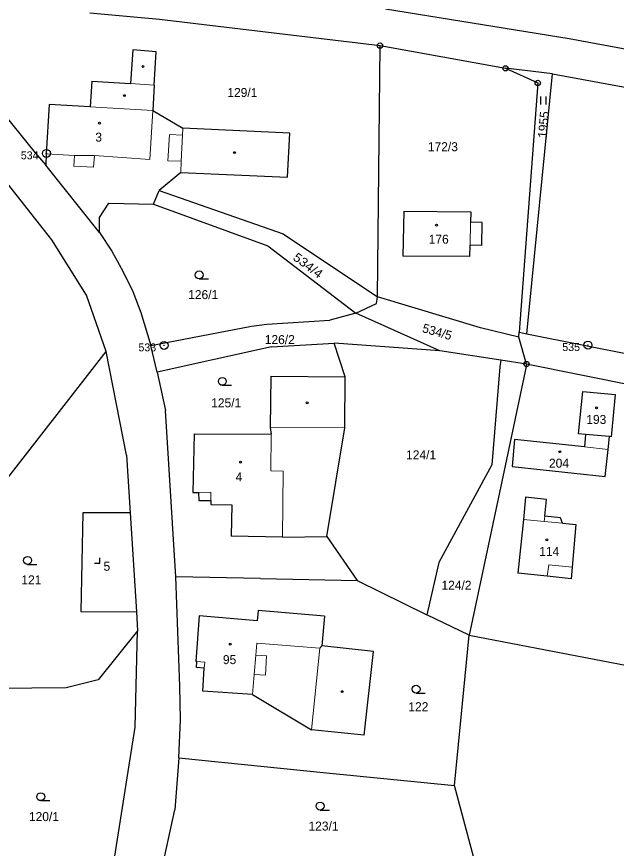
# Model space of a CAD drawing. Extents: x -601131 to -597152, y -1058536 to -1055911.
# Drawn here: x -599350.8 to -599237.3, y -1056634.8 to -1056477.3 of the extents above; entities that cross this region are included whole.
import ezdxf
from ezdxf.enums import TextEntityAlignment as Align

# ---------------------------------------------------------------- set-up
doc = ezdxf.new("R2010")
doc.units = 0
doc.header["$LTSCALE"] = 0.68
for name, color, linetype, lineweight in [('1', 7, 'Continuous', 25), ('3', 7, 'Continuous', 25), ('4', 7, 'Continuous', 13), ('5', 7, 'Continuous', 25), ('8', 7, 'Continuous', 25)]:
    doc.layers.add(name, color=color, linetype=linetype, lineweight=lineweight)
doc.layers.add('2', color=7, linetype='Continuous')

msp = doc.modelspace()

# ---------------------------------------------------------------- linework, layer by layer
at = {"layer": '1'}
for p, q in [((-599246.19, -1056481.54), (-599280.95, -1056475.91)), ((-599336.92, -1056476.64), (-599323.72, -1056477.85)), ((-599323.72, -1056477.85), (-599282, -1056482.83)), ((-599218.22, -1056486.75), (-599246.19, -1056481.54)), ((-599328.82, -1056483.65), (-599329.25, -1056490.01)), ((-599324.36, -1056483.98), (-599328.82, -1056483.65)), ((-599282.49, -1056530.39), (-599282, -1056482.83)), ((-599282, -1056482.83), (-599258.24, -1056487.13)), ((-599324.74, -1056490.29), (-599324.36, -1056483.98)), ((-599360.66, -1056486.62), (-599347.27, -1056503.12)), ((-599258.24, -1056487.13), (-599252.14, -1056489.89)), ((-599249.34, -1056488.19), (-599258.24, -1056487.13)), ((-599254.19, -1056537.36), (-599249.34, -1056488.19)), ((-599249.34, -1056488.19), (-599219.47, -1056493.64)), ((-599336.55, -1056489.57), (-599336.84, -1056494.42)), ((-599336.55, -1056489.57), (-599329.25, -1056490.01)), ((-599252.14, -1056489.89), (-599255.65, -1056537.07)), ((-599324.74, -1056490.29), (-599325.02, -1056495.08)), ((-599344.64, -1056493.95), (-599345.22, -1056503.29)), ((-599336.84, -1056494.42), (-599344.64, -1056493.95)), ((-599325.02, -1056495.08), (-599319.32, -1056498.47)), ((-599299.08, -1056499.43), (-599319.32, -1056498.47)), ((-599299.51, -1056507.74), (-599299.08, -1056499.43)), ((-599347.27, -1056503.12), (-599345.29, -1056505.47)), ((-599345.22, -1056503.29), (-599345.29, -1056505.47)), ((-599335.11, -1056518.19), (-599345.29, -1056505.47)), ((-599344.11, -1056519.56), (-599353.98, -1056507.19)), ((-599319.72, -1056506.84), (-599323.78, -1056510.24)), ((-599319.72, -1056506.84), (-599299.51, -1056507.74)), ((-599324.87, -1056512.83), (-599323.78, -1056510.24)), ((-599323.78, -1056510.24), (-599300.33, -1056518.48)), ((-599335.11, -1056515.35), (-599333.31, -1056512.65)), ((-599333.31, -1056512.65), (-599324.87, -1056512.83)), ((-599324.87, -1056512.83), (-599303.21, -1056520.71)), ((-599335.11, -1056518.19), (-599335.11, -1056515.35)), ((-599277.49, -1056514.17), (-599277.66, -1056522.67)), ((-599277.49, -1056514.17), (-599264.83, -1056514.3)), ((-599264.83, -1056514.3), (-599264.87, -1056516.25)), ((-599262.66, -1056516.34), (-599264.87, -1056516.25)), ((-599262.75, -1056520.67), (-599262.66, -1056516.34)), ((-599335.11, -1056518.19), (-599332.75, -1056521.76)), ((-599300.33, -1056518.48), (-599282.49, -1056530.39)), ((-599337.55, -1056530.08), (-599344.11, -1056519.56)), ((-599303.21, -1056520.71), (-599286.57, -1056533.49)), ((-599265.01, -1056522.74), (-599264.96, -1056520.58)), ((-599262.75, -1056520.67), (-599264.96, -1056520.58)), ((-599332.75, -1056521.76), (-599330.67, -1056525.5)), ((-599265.01, -1056522.74), (-599277.66, -1056522.67)), ((-599330.67, -1056525.5), (-599328.81, -1056529.37)), ((-599328.81, -1056529.37), (-599327.28, -1056533.36)), ((-599333.85, -1056540.74), (-599337.55, -1056530.08)), ((-599282.66, -1056531.62), (-599282.49, -1056530.39)), ((-599262.95, -1056536.25), (-599282.49, -1056530.39)), ((-599286.57, -1056533.49), (-599282.66, -1056531.62)), ((-599327.28, -1056533.36), (-599325.37, -1056539.59)), ((-599286.57, -1056533.49), (-599291.51, -1056534.81)), ((-599270.65, -1056540.61), (-599286.57, -1056533.49)), ((-599306.34, -1056535.96), (-599303.43, -1056535.56)), ((-599303.43, -1056535.56), (-599291.51, -1056534.81)), ((-599325.37, -1056539.59), (-599306.34, -1056535.96)), ((-599255.73, -1056538.03), (-599262.95, -1056536.25)), ((-599255.73, -1056538.03), (-599255.65, -1056537.07)), ((-599255.65, -1056537.07), (-599254.19, -1056537.36)), ((-599254.19, -1056537.36), (-599225.68, -1056543.1)), ((-599254.26, -1056543.1), (-599255.73, -1056538.03)), ((-599324.17, -1056544.62), (-599325.37, -1056539.59)), ((-599302.57, -1056539.87), (-599324.17, -1056544.62)), ((-599302.57, -1056539.87), (-599290.69, -1056539.12)), ((-599270.65, -1056540.61), (-599290.69, -1056539.12)), ((-599288.59, -1056545.49), (-599290.69, -1056539.12)), ((-599357.98, -1056571.68), (-599333.85, -1056540.74)), ((-599329.96, -1056560.36), (-599333.85, -1056540.74)), ((-599259.14, -1056542.37), (-599270.65, -1056540.61)), ((-599259.31, -1056543.64), (-599260.86, -1056562.16)), ((-599259.14, -1056542.37), (-599259.31, -1056543.64)), ((-599254.26, -1056543.1), (-599259.14, -1056542.37)), ((-599254.26, -1056543.1), (-599254.55, -1056544.47)), ((-599215.08, -1056551), (-599254.26, -1056543.1)), ((-599324.17, -1056544.62), (-599322.61, -1056551.91)), ((-599302.7, -1056545.38), (-599302.78, -1056555.13)), ((-599302.7, -1056545.38), (-599288.59, -1056545.49)), ((-599288.64, -1056555.18), (-599288.59, -1056545.49)), ((-599244.41, -1056556.29), (-599243.61, -1056548.27)), ((-599243.61, -1056548.27), (-599237.48, -1056548.88)), ((-599237.48, -1056548.88), (-599238.27, -1056556.87)), ((-599320.65, -1056583.35), (-599322.61, -1056551.91)), ((-599317.21, -1056556.29), (-599317.45, -1056567.4)), ((-599317.21, -1056556.29), (-599302.62, -1056556.39)), ((-599302.78, -1056555.13), (-599302.62, -1056556.39)), ((-599292.09, -1056575.75), (-599288.64, -1056555.18)), ((-599243.1, -1056556.41), (-599244.41, -1056556.29)), ((-599243.1, -1056556.41), (-599243.32, -1056558.79)), ((-599238.57, -1056556.84), (-599243.1, -1056556.41)), ((-599238.82, -1056559.27), (-599238.57, -1056556.84)), ((-599238.27, -1056556.87), (-599238.57, -1056556.84)), ((-599329.96, -1056560.36), (-599329.28, -1056571.26)), ((-599260.86, -1056562.16), (-599270.89, -1056580.69)), ((-599317.45, -1056567.4), (-599316.39, -1056567.39)), ((-599316.39, -1056567.39), (-599316.3, -1056568.93)), ((-599254.43, -1056568.31), (-599254.82, -1056572.53)), ((-599250.5, -1056568.76), (-599254.43, -1056568.31)), ((-599250.82, -1056571.87), (-599250.5, -1056568.76)), ((-599316.3, -1056568.93), (-599314, -1056568.94)), ((-599314, -1056568.94), (-599314, -1056569.68)), ((-599314, -1056569.68), (-599310.07, -1056569.74)), ((-599310.07, -1056569.74), (-599310.16, -1056575.67)), ((-599338.28, -1056571.26), (-599338.64, -1056589.94)), ((-599329.28, -1056571.26), (-599338.28, -1056571.26)), ((-599329.28, -1056571.26), (-599328.1, -1056589.99)), ((-599247.81, -1056572.22), (-599250.82, -1056571.87)), ((-599254.82, -1056572.53), (-599255.91, -1056582.67)), ((-599247.44, -1056573.24), (-599247.81, -1056572.22)), ((-599247.44, -1056573.24), (-599244.91, -1056573.48)), ((-599244.91, -1056573.48), (-599245.63, -1056581.52)), ((-599300.47, -1056575.86), (-599310.16, -1056575.67)), ((-599300.47, -1056575.86), (-599292.09, -1056575.75)), ((-599292.09, -1056575.75), (-599286.34, -1056584.1)), ((-599270.89, -1056580.69), (-599273.11, -1056590.58)), ((-599250.38, -1056583.24), (-599255.91, -1056582.67)), ((-599245.63, -1056581.52), (-599245.83, -1056583.73)), ((-599319.9, -1056604.06), (-599320.65, -1056583.35)), ((-599304.6, -1056583.69), (-599320.65, -1056583.35)), ((-599304.6, -1056583.69), (-599286.34, -1056584.1)), ((-599286.34, -1056584.1), (-599273.11, -1056590.58)), ((-599245.83, -1056583.73), (-599250.38, -1056583.24)), ((-599338.64, -1056589.94), (-599328.1, -1056589.99)), ((-599328.1, -1056589.99), (-599327.88, -1056593.57)), ((-599316.21, -1056590.77), (-599316.88, -1056599.4)), ((-599305.25, -1056591.68), (-599316.21, -1056590.77)), ((-599305.09, -1056589.76), (-599305.25, -1056591.68)), ((-599292.52, -1056590.8), (-599305.09, -1056589.76)), ((-599292.52, -1056590.8), (-599292.99, -1056596.46)), ((-599265.11, -1056594.43), (-599273.11, -1056590.58)), ((-599327.88, -1056593.57), (-599335.38, -1056602.87)), ((-599328.38, -1056611.8), (-599327.88, -1056593.57)), ((-599267.88, -1056622.9), (-599265.11, -1056594.43)), ((-599265.11, -1056594.43), (-599225.75, -1056602)), ((-599283.26, -1056597.54), (-599292.99, -1056596.46)), ((-599285, -1056613.32), (-599283.26, -1056597.54)), ((-599316.65, -1056599.42), (-599316.88, -1056599.4)), ((-599316.72, -1056600.53), (-599316.65, -1056599.42)), ((-599315.26, -1056600.67), (-599316.72, -1056600.53)), ((-599315.57, -1056605), (-599315.26, -1056600.67)), ((-599335.38, -1056602.87), (-599341.43, -1056604.36)), ((-599341.43, -1056604.36), (-599361.21, -1056604.62)), ((-599319.77, -1056610.47), (-599319.9, -1056604.06)), ((-599306.16, -1056605.65), (-599315.57, -1056605)), ((-599306.16, -1056605.65), (-599294.97, -1056612.34)), ((-599320.06, -1056617.66), (-599319.77, -1056610.47)), ((-599332.25, -1056636.61), (-599328.38, -1056611.8)), ((-599285, -1056613.32), (-599294.97, -1056612.34)), ((-599320.06, -1056617.66), (-599320.84, -1056627.49)), ((-599320.06, -1056617.66), (-599292.11, -1056620.45)), ((-599292.11, -1056620.45), (-599267.88, -1056622.9)), ((-599262.81, -1056641.86), (-599267.88, -1056622.9)), ((-599324.69, -1056645.02), (-599320.84, -1056627.49))]:
    msp.add_line(p, q, dxfattribs=at)
for points in [[(-599254.55, -1056544.47), (-599258.33, -1056562.36), (-599265.11, -1056594.43)], [(-599243.32, -1056558.79), (-599256.55, -1056557.38), (-599256.98, -1056562.47), (-599239.35, -1056564.39), (-599238.82, -1056559.27)]]:
    msp.add_lwpolyline(points, dxfattribs=at)
at = {"layer": '3'}
for p, q in [((-599251.531, -1056493.95), (-599251.531, -1056492.45)), ((-599250.53, -1056493.95), (-599250.53, -1056492.45)), ((-599316.233, -1056526.98), (-599314.483, -1056526.98)), ((-599311.853, -1056547.13), (-599310.103, -1056547.13)), ((-599348.713, -1056581.02), (-599346.963, -1056581.02)), ((-599275.173, -1056605.39), (-599273.423, -1056605.39)), ((-599346.223, -1056625.74), (-599344.473, -1056625.74)), ((-599293.343, -1056627.51), (-599291.593, -1056627.51))]:
    msp.add_line(p, q, dxfattribs=at)
msp.add_lwpolyline([(-599336.051, -1056580.76), (-599335.05, -1056580.76), (-599335.05, -1056579.76)], dxfattribs=at)
for centre in [(-599316.2329, -1056526.2298), (-599311.8529, -1056546.3798), (-599348.7129, -1056580.2698), (-599275.1729, -1056604.6398), (-599346.2229, -1056624.9898), (-599293.3429, -1056626.7598)]:
    msp.add_circle(centre, 0.75, dxfattribs=at)
at = {"layer": '4'}
for p, q in [((-599329.25, -1056490.01), (-599324.74, -1056490.29)), ((-599325.02, -1056495.08), (-599336.84, -1056494.42)), ((-599325.02, -1056495.08), (-599325.58, -1056504.36)), ((-599319.32, -1056498.47), (-599319.38, -1056499.78)), ((-599321.86, -1056499.66), (-599322.16, -1056504.61)), ((-599319.38, -1056499.78), (-599321.86, -1056499.66)), ((-599319.38, -1056499.78), (-599319.62, -1056504.73)), ((-599339.83, -1056503.62), (-599345.22, -1056503.29)), ((-599336.08, -1056503.65), (-599339.83, -1056503.62)), ((-599336.23, -1056505.82), (-599336.08, -1056503.65)), ((-599325.58, -1056504.36), (-599336.08, -1056503.65)), ((-599322.16, -1056504.61), (-599319.62, -1056504.73)), ((-599319.62, -1056504.73), (-599319.72, -1056506.84)), ((-599264.96, -1056520.58), (-599264.87, -1056516.25)), ((-599288.64, -1056555.18), (-599302.78, -1056555.13)), ((-599302.69, -1056563.32), (-599302.62, -1056556.39)), ((-599243.32, -1056558.79), (-599238.82, -1056559.27)), ((-599300.33, -1056563.35), (-599302.69, -1056563.32)), ((-599300.47, -1056575.86), (-599300.33, -1056563.35)), ((-599316.39, -1056567.39), (-599314.01, -1056567.38)), ((-599314.01, -1056567.38), (-599314, -1056568.94)), ((-599250.93, -1056572.9), (-599250.82, -1056571.87)), ((-599250.93, -1056572.9), (-599254.82, -1056572.53)), ((-599247.44, -1056573.24), (-599250.93, -1056572.9)), ((-599250.07, -1056581.12), (-599250.38, -1056583.24)), ((-599245.63, -1056581.52), (-599250.07, -1056581.12)), ((-599305.34, -1056595.9), (-599305.53, -1056598.19)), ((-599293.4, -1056596.85), (-599305.34, -1056595.9)), ((-599293.4, -1056596.85), (-599294.97, -1056612.34)), ((-599292.99, -1056596.46), (-599293.4, -1056596.85)), ((-599305.84, -1056601.84), (-599305.53, -1056598.19)), ((-599305.53, -1056598.19), (-599303.46, -1056598.32)), ((-599303.46, -1056598.32), (-599303.7, -1056602)), ((-599316.65, -1056599.42), (-599315.18, -1056599.52)), ((-599315.18, -1056599.52), (-599315.26, -1056600.67)), ((-599305.84, -1056601.84), (-599306.16, -1056605.65)), ((-599303.7, -1056602), (-599305.84, -1056601.84))]:
    msp.add_line(p, q, dxfattribs=at)
msp.add_lwpolyline([(-599339.83, -1056503.62), (-599339.96, -1056505.65), (-599336.23, -1056505.82)], dxfattribs=at)
at = {"layer": '5'}
for centre in [(-599326.8668, -1056486.7692), (-599330.3968, -1056492.2992), (-599335.1068, -1056497.5092), (-599309.5568, -1056503.0892), (-599271.3168, -1056516.8192), (-599295.7968, -1056550.4292), (-599240.9968, -1056551.3992), (-599247.9668, -1056559.6992), (-599308.3868, -1056561.6892), (-599250.4068, -1056576.3892), (-599310.3468, -1056596.1292), (-599289.1768, -1056605.0992)]:
    msp.add_circle(centre, 0.175, dxfattribs=at)
at = {"layer": '8'}
for centre, radius in [((-599282, -1056482.8299), 0.5), ((-599282, -1056482.8299), 0.0303), ((-599258.24, -1056487.1299), 0.5), ((-599258.24, -1056487.1299), 0.0303), ((-599252.14, -1056489.8899), 0.5), ((-599252.14, -1056489.8899), 0.0303), ((-599345.15, -1056503.2298), 0.75), ((-599345.15, -1056503.2298), 0.03), ((-599322.88, -1056539.5798), 0.75), ((-599242.65, -1056539.5198), 0.75), ((-599322.88, -1056539.5798), 0.03), ((-599242.65, -1056539.5198), 0.03), ((-599254.26, -1056543.0999), 0.5), ((-599254.26, -1056543.0999), 0.0303)]:
    msp.add_circle(centre, radius, dxfattribs=at)

# ---------------------------------------------------------------- texts
at = {"layer": '2'}
for s, p in [('129/1', (-599310.9, -1056492.554)), ('3', (-599335.89, -1056501.005)), ('172/3', (-599272.94, -1056502.814)), ('176', (-599272.78, -1056520.324)), ('126/1', (-599318.32, -1056530.814)), ('126/2', (-599303.82, -1056539.324)), ('125/1', (-599313.96, -1056551.295)), ('124/1', (-599277.07, -1056561.135)), ('4', (-599309.33, -1056565.304)), ('114', (-599251.86, -1056579.405)), ('5', (-599334.34, -1056582.225)), ('121', (-599349.89, -1056584.795)), ('124/2', (-599270.37, -1056585.814)), ('95', (-599311.74, -1056599.895)), ('122', (-599276.64, -1056608.804)), ('120/1', (-599348.46, -1056629.604)), ('123/1', (-599295.54, -1056631.405))]:
    msp.add_text(s, height=1.7, dxfattribs=at).set_placement(p)
for s, rotation, p in [('1955', 85, (-599250.218, -1056497.8541)), ('534/5', 344, (-599271.4078, -1056537.8119))]:
    msp.add_text(s, height=1.7, rotation=rotation, dxfattribs=at).set_placement(p, align=Align.CENTER)
at = {"layer": '2', "width": 1.1}
msp.add_text('534/4', height=1.7, rotation=323, dxfattribs=at).set_placement((-599298.635, -1056523.229))
at = {"layer": '2'}
for s, p in [('193', (-599241.059, -1056554.435)), ('204', (-599248.119, -1056562.715))]:
    msp.add_text(s, height=1.7, dxfattribs=at).set_placement(p, align=Align.CENTER)
at = {"layer": '8'}
for s, p in [('534', (-599346.649, -1056504.347)), ('533', (-599324.379, -1056540.697)), ('535', (-599244.149, -1056540.637))]:
    msp.add_text(s, height=1.5, dxfattribs=at).set_placement(p, align=Align.RIGHT)

doc.saveas('drawing.dxf')
